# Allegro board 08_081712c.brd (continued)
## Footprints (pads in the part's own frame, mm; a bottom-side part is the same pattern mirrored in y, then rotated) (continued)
SWSML106W240H140
  rect 1.524x2.032 smd: 1(0,-4.516) 2(0,4.516)
SWSML335W142H220
  rect 0.991x1.6 smd: 1(-2.5,-1.2) 2(0,1.2) 3(2.5,-1.2)
SWSML837W244H153
  rect 1.092x1.499 smd: 1(-8.89,-4.451) 2(-6.35,-4.451) 3(-3.81,-4.451) 4(-1.27,-4.451) 5(1.27,-4.451) 6(3.81,-4.451) 7(6.35,-4.451) 8(8.89,-4.451) 9(8.89,4.451) 10(6.35,4.451) 11(3.81,4.451) 12(1.27,4.451) 13(-1.27,4.451) 14(-3.81,4.451) 15(-6.35,4.451) 16(-8.89,4.451)
SWSML858W263H160
  rect 1.118x2.438 smd: 1A(-8.89,-4.305) 1B(-8.89,4.305) 2A(-6.35,-4.305) 2B(-6.35,4.305) 3A(-3.81,-4.305) 3B(-3.81,4.305) 4A(-1.27,-4.305) 4B(-1.27,4.305) 5A(1.27,-4.305) 5B(1.27,4.305) 6A(3.81,-4.305) 6B(3.81,4.305) 7A(6.35,-4.305) 7B(6.35,4.305) 8A(8.89,-4.305) 8B(8.89,4.305)
SWSML1110W450H237
  rect 2.032x2.032 smd: 1(11.082,-4.42) 2(11.082,0) 3(11.082,4.42) 4(-8.776,4.414) 5(-8.776,-4.414)
TPC65D45
  round 1.651 hole 1.143: 1(0,0)
TPSMC30
  round 0.762 smd: 1(0,0)
TSSOP14
  rect 1.651x0.33 smd: 1(-2.87,1.956) 2(-2.87,1.306) 3(-2.87,0.655) 4(-2.87,0.005) 5(-2.87,-0.645) 6(-2.87,-1.295) 7(-2.87,-1.946) 8(2.87,-1.946) 9(2.87,-1.295) 10(2.87,-0.645) 11(2.87,0.005) 12(2.87,0.655) 13(2.87,1.306) 14(2.87,1.956)
unnamed
  round 4.445 hole 3.175 unplated: (0,0)
UPAK6
  rect 0.305x0.533 smd: 1(-0.5,-0.35)
  rect 0.305x0.483 smd: 2(0,-0.375) 3(0.5,-0.375) 4(0.5,0.375) 5(0,0.375) 6(-0.5,0.375)
UQFN12_2X1_7
  custom 0.102x0.102 smd: 1(-0.8,-0.655)
  rect 0.203x0.61 smd: 2(-0.4,-0.655) 3(0,-0.655) 4(0.4,-0.655) 5(0.8,-0.655) 7(0.8,0.655) 8(0.4,0.655) 9(0,0.655) 10(-0.4,0.655) 11(-0.8,0.655)
  rect 0.61x0.203 smd: 6(0.805,0) 12(-0.805,0)
VSSOP16
  rect 0.279x0.838 smd: 1(-1.75,-1.823) 2(-1.25,-1.823) 3(-0.75,-1.823) 4(-0.25,-1.823) 5(0.25,-1.823) 6(0.75,-1.823) 7(1.25,-1.823) 8(1.75,-1.823) 9(1.75,1.823) 10(1.25,1.823) 11(0.75,1.823) 12(0.25,1.823) 13(-0.25,1.823) 14(-0.75,1.823) 15(-1.25,1.823) 16(-1.75,1.823)
WLCSP4H26
  round 0.203 smd: A1(-0.2,-0.2) A2(-0.2,0.2) B1(0.2,-0.2) B2(0.2,0.2)
WSON8_5X6_PAD4X3_4
  oval 0.432x0.94 smd: 1(-1.905,-2.735) 2(-0.635,-2.735) 3(0.635,-2.735) 4(1.905,-2.735) 5(1.905,2.735) 6(0.635,2.735) 7(-0.635,2.735) 8(-1.905,2.735)
  rect 3.988x3.404 smd: PAD(0,0)
YSML79W63H32
  rect 0.762x0.66 smd: 1(-0.66,-0.508) 2(0.66,-0.508) 3(0.66,0.508) 4(-0.66,0.508)
YSML98W79H35
  rect 1.092x0.991 smd: 1(-0.921,-0.72) 2(0.921,-0.72) 3(0.921,0.72) 4(-0.921,0.72)
YSML126W59H26
  rect 0.991x1.803 smd: 1(-1.245,0) 2(1.245,0)
YSML126W98H31
  rect 1.397x1.194 smd: 1(-1.1,-0.95) 2(1.1,-0.95) 3(1.1,0.95) 4(-1.1,0.95)

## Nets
0V9: C18.1 C19.1 C20.1 C22.1 C28.1 C31.1 C70.1 C388.1 C389.1 L4.2(N2) TP14.1(N1) U1.4 U1.28 U1.36
0V9_B: C44.1 C45.1 C46.1 C48.1 C50.1 C52.1 C54.1 C57.1 C71.1 L3.2(N2) TP15.1(N1) U2.4 U2.28 U2.36
3V3: C17.1 C21.1 C25.1 C27.1 C29.1 C30.1 C43.1 C47.1 C49.1 C51.1 C53.1 C55.1 C56.1 C69.1 C76.1 C77.1 C78.1 C83.1 C84.1 C85.1 C86.1 C87.1 C88.1 C89.1 C90.1 C93.1 C94.1 C97.1 C98.1 C101.1 C102.1 C105.1 C106.1 C107.1 C108.1 C171.1 C172.1 C173.1 C177.1 C178.1 C184.1 C185.1 C187.1 C189.1 C190.1 C192.1 C193.1 C194.1 C195.1 C196.1 C197.1 C198.1 C315.2(N2) C317.1 C373.1 C374.1 C375.1 C378.1 C379.1 C380.1 C385.1 C387.1 C390.1 C393.1 C398.1 C429.1 C431.1 C432.1 L6.1 M1.1 M1.5 M2.1 M2.5 P1.20 P2.20 Q1.3(E) R68.1 R79.2(N2) R100.1 R111.2(N2) R127.1 R128.1 R129.1 R130.1 R131.2(N2) R132.2(N2) R138.2(N2) R140.2(N2) R267.1 R269.1 R271.1 R273.1 R284.1 R362.1 R363.1 R370.1 R371.1 R451.2(N2) R455.2(N2) R568.1 TP20.1(N1) U1.11 U1.20 U2.11 U2.20 U13.1 U13.2 U13.6 U16.11(REF_B) U17.11(REF_B) U18.4 U18.12 U18.31 U18.40 U19.4 U19.12 U19.31 U19.40 U20.11(REF_B) U21.11(REF_B) U30.11 U31.11 U32.11(REF_B) U33.3 U33.12 U33.22 U33.25 U33.39 U33.49 U33.58 U63.11(REF_B) U68.11(REF_B) U70.8(VCC) U71.5 U72.8(VCC) U73.5 U79.11(REF_B) U80.11(REF_B) U81.1 U81.12 Y1.1 Y1.4(VDD) Y2.1 Y2.4(VDD) Y3.1 Y3.4(VCC)
5V: A1.5 A2.5 C109.1 C110.1 C274.1 C275.1 C276.1 C277.1 C284.1 C285.1 C286.1 C287.1 C316.2(N2) C318.1 L7.1 R158.1 R161.1 R164.1 R167.1 R186.1 R189.1 R192.1 R195.1 R214.1 R217.1 R220.1 R223.1 R242.1 R245.1 R248.1 R251.1 R452.2(N2) R456.2(N2) TP21.1(N1) U41.14(VDD2) U42.14(VDD2) U43.14(VDD2) U44.14(VDD2)
5V_SOM_A: C419.2(N2) C420.1 L9.1 R592.2(N2) R594.2(N2) SOMA.E1 SOMA.E2 TP30.1(N1)
5V_SOM_B: C425.2(N2) C426.1 L10.1 R596.2(N2) R598.2(N2) SOMB.E1 SOMB.E2 TP31.1(N1)
10V: C111.1 C112.1 C125.1 C126.1 C139.1 C140.1 C153.1 C154.1 C304.2(N2) C306.1 L1.1 R442.2(N2) R446.2(N2) TP17.1(N1) U22.8 U23.8 U24.8 U25.8 U26.8 U27.8 U28.8 U29.8
12V: C302.2(N2) C307.1 C308.1 C319.1 C320.1 C421.1 C427.1 D10.C D11.C J4.95 J4.97 J4.99 J5.95 J5.97 J5.99 P3.95 P3.97 P3.99 P4.95 P4.97 P4.99 R460.2(N2) TP18.1(N1) TP19.1(N1) TP22.1(N1) U3.9(VIN) U4.9(VIN) U49.9(VIN) U50.9(VIN) U77.9(VIN) U78.9(VIN)
DGND: A1.2(V-) A2.2(V-) C1.2(N2) C2.2(N2) C3.2(N2) C4.2(N2) C5.2(N2) C6.2(N2) C7.2(N2) C8.2(N2) C9.2(N2) C10.2(N2) C11.2(N2) C12.2(N2) C13.2(N2) C14.1 C15.1 C16.1 C17.2(N2) C18.2(N2) C19.2(N2) C20.2(N2) C21.2(N2) C22.2(N2) C23.2(N2) C24.2(N2) C25.2(N2) C26.2(N2) C27.2(N2) C28.2(N2) C29.2(N2) C30.2(N2) C31.2(N2) C32.2(N2) C33.2(N2) C34.2(N2) C35.2(N2) C36.2(N2) C37.2(N2) C38.2(N2) C39.2(N2) C40.2(N2) C41.2(N2) C42.2(N2) C43.2(N2) C44.2(N2) C45.2(N2) C46.2(N2) C47.2(N2) C48.2(N2) C49.2(N2) C50.2(N2) C51.2(N2) C52.2(N2) C53.2(N2) C54.2(N2) C55.2(N2) C56.2(N2) C57.2(N2) C58.2(N2) C59.2(N2) C60.2(N2) C61.2(N2) C62.2(N2) C63.2(N2) C64.2(N2) C65.2(N2) C66.2(N2) C67.2(N2) C68.2(N2) C69.2(N2) C70.2(N2) C71.2(N2) C72.2(N2) C73.2(N2) C74.2(N2) C75.2(N2) C76.2(N2) C77.2(N2) C78.2(N2) C79.2(N2) C80.2(N2) C81.2(N2) C82.2(N2) C85.2(N2) C86.2(N2) C89.2(N2) C90.2(N2) C91.2(N2) C92.2(N2) C93.2(N2) C94.2(N2) C95.2(N2) C96.2(N2) C97.2(N2) C98.2(N2) C99.2(N2) C100.2(N2) C101.2(N2) C102.2(N2) C103.2(N2) C104.2(N2) C105.2(N2) C106.2(N2) C107.2(N2) C108.2(N2) C109.2(N2) C110.2(N2) C111.2(N2) C112.2(N2) C125.2(N2) C126.2(N2) C139.2(N2) C140.2(N2) C153.2(N2) C154.2(N2) C168.2(N2) C169.2(N2) C170.2(N2) C171.2(N2) C172.2(N2) C173.2(N2) C175.2(N2) C177.2(N2) C178.2(N2) C179.2(N2) C180.2(N2) C181.2(N2) C182.2(N2) C183.2(N2) C184.2(N2) C185.2(N2) C186.2(N2) C187.2(N2) C188.2(N2) C189.2(N2) C191.2(N2) C192.2(N2) C194.2(N2) C195.2(N2) C196.2(N2) C197.2(N2) C198.2(N2) C199.2(N2) C200.2(N2) C201.2(N2) C202.2(N2) C203.2(N2) C204.2(N2) C205.2(N2) C206.2(N2) C215.2(N2) C216.2(N2) C217.2(N2) C218.2(N2) C219.2(N2) C220.2(N2) C221.2(N2) C222.2(N2) C231.2(N2) C232.2(N2) C233.2(N2) C234.2(N2) C235.2(N2) C236.2(N2) C237.2(N2) C238.2(N2) C247.2(N2) C248.2(N2) C249.2(N2) C250.2(N2) C255.2(N2) C256.2(N2) C257.2(N2) C258.2(N2) C263.2(N2) C264.2(N2) C265.2(N2) C266.2(N2) C267.2(N2) C268.2(N2) C269.2(N2) C270.2(N2) C271.2(N2) C272.2(N2) C273.2(N2) C274.2(N2) C275.2(N2) C276.2(N2) C277.2(N2) C278.2(N2) C279.2(N2) C280.2(N2) C281.2(N2) C282.2(N2) C283.2(N2) C284.2(N2) C285.2(N2) C286.2(N2) C287.2(N2) C288.2(N2) C289.2(N2) C290.2(N2) C291.2(N2) C292.2(N2) C293.2(N2) C294.2(N2) C295.2(N2) C296.2(N2) C298.1 C300.2(N2) C301.2(N2) C302.1 C305.2(N2) C306.2(N2) C307.2(N2) C308.2(N2) C309.2(N2) C310.2(N2) C313.2(N2) C314.2(N2) C317.2(N2) C318.2(N2) C319.2(N2) C320.2(N2) C321.2(N2) C322.2(N2) C323.2(N2) C324.2(N2) C325.2(N2) C326.2(N2) C327.2(N2) C328.2(N2) C329.2(N2) C330.2(N2) C331.2(N2) C332.2(N2) C333.2(N2) C334.2(N2) C335.2(N2) C336.2(N2) C337.2(N2) C338.2(N2) C339.2(N2) C340.2(N2) C341.2(N2) C342.2(N2) C343.2(N2) C344.2(N2) C345.2(N2) C346.2(N2) C347.2(N2) C348.2(N2) C349.2(N2) C350.2(N2) C352.2(N2) C353.2(N2) C354.2(N2) C355.2(N2) C356.2(N2) C357.2(N2) C358.2(N2) C359.2(N2) C360.2(N2) C361.2(N2) C362.2(N2) C363.2(N2) C364.2(N2) C365.2(N2) C366.2(N2) C367.2(N2) C368.2(N2) C369.2(N2) C370.2(N2) C371.2(N2) C372.2(N2) C373.2(N2) C374.2(N2) C375.2(N2) C376.2(N2) C377.2(N2) C378.2(N2) C379.2(N2) C380.2(N2) C381.2(N2) C382.2(N2) C383.2(N2) C384.2(N2) C385.2(N2) C387.2(N2) C388.2(N2) C389.2(N2) C390.2(N2) C392.2(N2) C393.2(N2) C394.2(N2) C395.2(N2) C396.2(N2) C398.2(N2) C415.1 C416.2(N2) C418.2(N2) C420.2(N2) C421.2(N2) C422.2(N2) C424.2(N2) C426.2(N2) C427.2(N2) C428.2(N2) C429.2(N2) C430.2(N2) C431.2(N2) C432.2(N2) C433.2(N2) D1.2 D2.2 D3.2 D4.2 D5.3(N3) D6.3(N3) D7.3(N3) D8.3(N3) D9.A(P) D11.A(P) D13.2 DS21.C DS22.C J1.S J2.S J4.1 J4.2 J4.5 J4.6 J4.9 J4.10 J4.13 J4.14 J4.17 J4.18(N9) J4.21 J4.22 J4.25 J4.26 J4.29 J4.30 J4.33 J4.34 J4.37 J4.38 J4.41 J4.42 J4.45 J4.46 J4.49 J4.50 J4.53 J4.54 J4.57 J4.58 J4.61 J4.62 J4.65 J4.66 J4.69 J4.70 J4.73 J4.74 J4.77 J4.78 J4.81 J4.82 J4.86 J4.89 J4.90 J4.91 J4.92 J4.93 J4.94 J5.1 J5.2 J5.5 J5.6 J5.9 J5.10 J5.13 J5.14 J5.17 J5.18(N9) J5.21 J5.22 J5.25 J5.26 J5.29 J5.30 J5.33 J5.34 J5.37 J5.38 J5.41 J5.42 J5.45 J5.46 J5.49 J5.50 J5.53 J5.54 J5.57 J5.58 J5.61 J5.62 J5.65 J5.66 J5.69 J5.70 J5.73 J5.74 J5.77 J5.78 J5.81 J5.82 J5.86 J5.89 J5.90 J5.91 J5.92 J5.93 J5.94 M1.2 M1.6 M2.2 M2.6 P3.1 P3.2 P3.5 P3.6 P3.9 P3.10 P3.13 P3.14 P3.17 P3.18(N9) P3.21 P3.22 P3.25 P3.26 P3.29 P3.30 P3.33 P3.34 P3.37 P3.38 P3.41 P3.42 P3.45 P3.46 P3.49 P3.50 P3.53 P3.54 P3.57 P3.58 P3.61 P3.62 P3.65 P3.66 P3.69 P3.70 P3.73 P3.74 P3.77 P3.78 P3.81 P3.82 P3.86 P3.89 P3.90 P3.91 P3.92 P3.93 P3.94 P4.1 P4.2 P4.5 P4.6 P4.9 P4.10 P4.13 P4.14 P4.17 P4.18(N9) P4.21 P4.22 P4.25 P4.26 P4.29 P4.30 P4.33 P4.34 P4.37 P4.38 P4.41 P4.42 P4.45 P4.46 P4.49 P4.50 P4.53 P4.54 P4.57 P4.58 P4.61 P4.62 P4.65 P4.66 P4.69 P4.70 P4.73 P4.74 P4.77 P4.78 P4.81 P4.82 P4.86 P4.89 P4.90 P4.91 P4.92 P4.93 P4.94 P5.2 P5.4 P5.6 P5.8 P5.10 P5.12 P5.14 P5.16 P6.2 P6.4 P6.6 P6.8 P6.10 P6.12 P6.14 P6.16 P7.2 P7.3(N3) P9.A1 P9.A12 P9.B1 P9.B12 P9.GND1 P9.GND2 P9.SH1 P9.SH2 P9.SH3 P9.SH4 P9.SH5 P9.SH6 P11.1 P11.GND1 P11.GND2 P11.GND3 P11.GND4 P12.1 P12.GND1 P12.GND2 P12.GND3 P12.GND4 P13.1 P13.GND1 P13.GND2 P13.GND3 P13.GND4 P14.2A P14.2B P14.5A P14.5B P14.8A P14.8B P14.11A P14.11B P14.16A P14.16B P14.19A P14.19B P14.22A P14.22B P14.25A P14.25B P14.SH1 P14.SH2 P14.SH3 P14.SH4 P15.1 P15.GND1 P15.GND2 P15.GND3 P15.GND4 P16.2 P16.5 P16.8 P16.11 P16.16 P16.19 P16.22 P16.25 P18.1_3 P18.1_5 P18.1_6 P18.2_3 P18.2_5 P18.2_6 P19.1_3 P19.1_5 P19.1_6 P19.2_3 P19.2_5 P19.2_6 P20.2 P20.4 P20.6 P20.8 P20.10 P20.12 P20.14 P20.16 P20.18 P20.20 P21.2 P21.4 P21.6 P21.8 P21.10 P21.12 P21.14 P21.16 P21.18 P21.20 P22.1 P23.1 P24.1 P25.1 P26.1 P27.1 P30.8 P30.12 P31.8 P31.12 P32.5 P32.7 P32.9(N9) P32.11 P33.5 P33.7 P33.9(N9) P33.11 P34.3 P34.5 P35.3 P35.5 P35.15 P35.17 P35.19 P37.1 P37.2 P37.11 P37.12 P38.4(N4) P39.2 P39.4 P39.6 P39.8 P39.10 P39.12 P39.14 P39.16 P39.18 P39.20 P40.2 P40.4 P40.6 P40.8 P40.10 P40.12 P40.14 P40.16 P40.18 P40.20 P42.4(N4) PB1.1 PB1.2(NO) PB2.1 PB2.2(NO) PB3.1 PB3.2(NO) PB4.1 PB4.2(NO) R22.2(N2) R23.2(N2) R25.2(N2) R26.2(N2) R27.2(N2) R28.2(N2) R29.2(N2) R30.2(N2) R34.2(N2) R36.2(N2) R51.2(N2) R53.1 R55.1 R57.1 R59.1 R61.1 R67.1 R72.1 R75.1 R77.1 R80.1 R85.1 R87.1 R89.1 R91.1 R93.1 R99.1 R104.1 R107.1 R109.1 R112.1 R117.2(N2) R119.2(N2) R121.2(N2) R122.2(N2) R124.2(N2) R125.2(N2) R133.2(N2) R134.2(N2) R137.2(N2) R139.2(N2) R149.2(N2) R150.2(N2) R153.2(N2) R154.2(N2) R155.2(N2) R156.2(N2) R177.2(N2) R178.2(N2) R179.2(N2) R180.2(N2) R181.2(N2) R182.2(N2) R183.2(N2) R184.2(N2) R205.2(N2) R206.2(N2) R207.2(N2) R208.2(N2) R209.2(N2) R210.2(N2) R211.2(N2) R212.2(N2) R233.2(N2) R234.2(N2) R235.2(N2) R236.2(N2) R237.2(N2) R238.2(N2) R239.2(N2) R240.2(N2) R261.2(N2) R262.2(N2) R263.2(N2) R264.2(N2) R266.2(N2) R278.2(N2) R282.2(N2) R283.2(N2) R293.2(N2) R294.2(N2) R295.2(N2) R296.2(N2) R297.2(N2) R298.2(N2) R299.2(N2) R300.2(N2) R309.2(N2) R310.2(N2) R311.2(N2) R312.2(N2) R313.2(N2) R314.2(N2) R315.2(N2) R316.2(N2) R325.2(N2) R326.2(N2) R327.2(N2) R328.2(N2) R329.2(N2) R330.2(N2) R331.2(N2) R332.2(N2) R337.2(N2) R338.2(N2) R339.2(N2) R340.2(N2) R345.2(N2) R346.2(N2) R347.2(N2) R348.2(N2) R349.2(N2) R350.2(N2) R351.2(N2) R352.2(N2) R353.2(N2) R354.2(N2) R355.2(N2) R356.2(N2) R357.2(N2) R364.2(N2) R365.2(N2) R384.1 R385.1 R386.1 R387.1 R408.2(N2) R409.2(N2) R410.2(N2) R411.2(N2) R420.2(N2) R421.2(N2) R422.2(N2) R423.2(N2) R424.2(N2) R425.2(N2) R426.2(N2) R427.2(N2) R428.2(N2) R429.2(N2) R430.2(N2) R431.2(N2) R438.2(N2) R439.2(N2) R440.2(N2) R443.2(N2) R444.2(N2) R447.2(N2) R448.2(N2) R449.2(N2) R450.2(N2) R453.2(N2) R454.2(N2) R457.2(N2) R458.2(N2) R459.1 R463.2(N2) R465.2(N2) R473.2(N2) R479.2(N2) R480.2(N2) R482.2(N2) R483.2(N2) R491.2(N2) R496.2(N2) R504.2(N2) R505.2(N2) R506.2(N2) R507.2(N2) R508.2(N2) R522.2(N2) R523.2(N2) R524.2(N2) R525.2(N2) R533.2(N2) R534.2(N2) R537.2(N2) R538.2(N2) R541.2(N2) R542.2(N2) R545.2(N2) R550.2(N2) R553.2(N2) R556.2(N2) R557.2(N2) R564.2(N2) R567.2(N2) R569.2(N2) R572.2(N2) R590.2(N2) R591.2(N2) R593.2(N2) R595.2(N2) R597.2(N2) S1.3(NO) S2.3(NO) S14.2(NO) SOMA.27 SOMA.28 SOMA.49 SOMA.50 SOMA.71 SOMA.72 SOMA.73 SOMA.85 SOMA.90 SOMA.97 SOMA.109 SOMA.110 SOMA.121 SOMA.124 SOMA.133 SOMA.134 SOMA.145 SOMA.148 SOMA.154 SOMA.157 SOMA.160 SOMA.166 SOMA.169 SOMA.174 SOMA.180 SOMA.181 SOMA.186 SOMA.191 SOMA.193 SOMA.196 SOMA.203 SOMA.206 SOMA.213 SOMA.216 SOMA.223 SOMA.229 SOMA.235 SOMA.238 SOMA.251 SOMA.260 SOMA.262 SOMA.265 SOMA.268 SOMA.272 SOMA.278 SOMA.279 SOMA.280 SOMA.281 SOMA.E3 SOMA.E4 SOMA.SH1 SOMA.SH2(N2) SOMB.27 SOMB.28 SOMB.49 SOMB.50 SOMB.71 SOMB.72 SOMB.73 SOMB.85 SOMB.90 SOMB.97 SOMB.109 SOMB.110 SOMB.121 SOMB.124 SOMB.133 SOMB.134 SOMB.145 SOMB.148 SOMB.154 SOMB.157 SOMB.160 SOMB.166 SOMB.169 SOMB.174 SOMB.180 SOMB.181 SOMB.186 SOMB.191 SOMB.193 SOMB.196 SOMB.203 SOMB.206 SOMB.213 SOMB.216 SOMB.223 SOMB.229 SOMB.235 SOMB.238 SOMB.251 SOMB.260 SOMB.262 SOMB.265 SOMB.268 SOMB.272 SOMB.278 SOMB.279 SOMB.280 SOMB.281 SOMB.E3 SOMB.E4 SOMB.SH1 SOMB.SH2(N2) TP25.1(N1) TP26.1(N1) TP27.1(N1) TP28.1(N1) TP29.1(N1) U1.5 U1.PAD U2.5 U2.PAD U3.PAD U4.PAD U5.2 U6.2 U7.7 U8.19 U8.PAD U9.7 U9.11 U9.12 U10.2 U11.3 U12.3 U13.3 U13.PAD U14.8 U15.8 U16.6 U17.6 U18.1 U18.5 U18.11 U18.21 U18.22 U18.28 U18.29 U18.PAD U19.1 U19.5 U19.11 U19.21 U19.22 U19.28 U19.29 U19.PAD U20.6 U21.6 U22.4(-VS) U23.4(-VS) U24.4(-VS) U25.4(-VS) U26.4(-VS) U27.4(-VS) U28.4(-VS) U29.4(-VS) U30.6 U31.6 U32.6 U33.13 U33.14 U33.21 U33.26 U33.30 U33.40 U33.48 U33.61 U33.80 U34.8 U35.8 U36.8 U37.8 U38.8 U39.8 U40.8 U41.2 U41.8 U41.9 U41.13 U41.16 U42.2 U42.8 U42.9 U42.13 U42.16 U43.2 U43.8 U43.9 U43.13 U43.16 U44.2 U44.8 U44.9 U44.13 U44.16 U45.8 U46.8 U47.8 U48.8 U49.PAD U50.PAD U51.19 U51.PAD U52.8 U52.12 U52.13 U52.14 U53.4 U53.PAD U54.B3 U54.B5 U54.C5 U54.D3 U54.D9 U54.D10 U54.E2 U54.E3 U54.H10 U54.K4 U54.K8 U55.PAD U56.1 U57.B2 U58.8 U58.9 U58.PAD U59.3 U60.2 U60.3 U60.8 U60.9 U60.PAD U61.8 U61.9 U61.10 U61.11 U61.12 U61.13 U61.14 U62.8 U62.9 U62.10 U62.11 U62.12 U62.13 U62.14 U63.6 U64.3 U65.B3 U65.C1 U65.E5(VSSQ_2) U66.1 U66.9 U67.5 U67.6 U67.7 U67.8 U67.12 U67.13 U67.14 U68.6 U69.5 U69.6 U69.7 U69.8 U69.12 U69.13 U69.14 U70.5 U71.3 U72.5 U73.3 U74.7 U75.7 U76.2 U77.PAD U78.PAD U79.6 U80.4 U80.5 U80.6 U80.7 U80.8 U81.4 U81.5 U81.6 U81.7(YB4) U81.8 Y1.2 Y2.2 Y3.2 Y6.2 Y6.4
GND_FIELD: P1.13 P1.14 P1.SH1 P1.SH2 P2.13 P2.14 P2.SH1 P2.SH2
VBUS_DETECT: C345.1 R481.2(N2) R482.1 U54.J11
VDDIO: C5.1 C6.1 C7.1 C8.1 C9.1 C10.1 C11.1 C12.1 C13.1 C14.2(N2) C15.2(N2) C16.2(N2) C23.1 C24.1 C26.1 C32.1 C33.1 C34.1 C35.1 C36.1 C38.1 C42.1 C58.1 C59.1 C60.1 C61.1 C62.1 C64.1 C68.1 C72.1 C73.1 C74.1 C75.1 C91.1 C92.1 C168.1 C169.1 C170.1 C263.1 C264.1 C265.1 C266.1 C267.1 C268.1 C269.1 C270.1 C271.1 C272.1 C273.1 C280.1 C281.1 C282.1 C283.1 C290.1 C291.1 C292.1 C293.1 C295.1 C303.2(N2) C305.1 C369.1 C370.1 C371.1 C372.1 C376.1 C377.1 C381.1 C382.1 C394.1 C396.1 C428.1 C430.1 C433.1 DS23.A(P) L5.1 P1.17 P2.17 R2.1 R3.1 R4.1 R5.1 R6.1 R7.1 R13.1 R14.1 R15.1 R16.1 R21.1 R24.1 R31.1 R32.1 R33.1 R35.1 R50.1 R52.2(N2) R54.2(N2) R58.2(N2) R60.2(N2) R62.2(N2) R66.2(N2) R71.2(N2) R74.2(N2) R76.2(N2) R78.1 R81.1 R84.2(N2) R86.2(N2) R90.2(N2) R92.2(N2) R94.2(N2) R98.2(N2) R103.2(N2) R106.2(N2) R108.2(N2) R110.1 R113.1 R120.1 R432.2(N2) R433.2(N2) R434.2(N2) R435.2(N2) R436.2(N2) R437.2(N2) R441.2(N2) R445.2(N2) R462.1 R509.2(N2) R510.2(N2) R511.2(N2) R512.2(N2) R513.2(N2) R514.1 R517.1 R528.1 R529.1 R530.1 R531.1 R535.1 R536.1 R539.1 R540.1 R543.1 R544.1 R546.1 R547.1 R548.1 R549.1 R551.1 R554.1 R555.1 R558.1 R559.1 R560.1 R561.1 R562.1 R563.1 R585.1 R588.1 R589.1 S11.1 S15.2(B) TP16.1(N1) U1.25 U1.31 U1.40 U2.25 U2.31 U2.40 U5.5(VCC) U6.5(VCC) U7.14(VCC) U8.21(VCC) U9.14(VCC) U10.4 U11.6 U12.6 U14.16(VCC) U15.16(VCC) U16.1 U16.12 U17.1 U17.12 U20.1 U20.12 U21.1 U21.12 U30.1 U30.12 U31.1 U31.12 U32.1 U32.12 U34.16(VCC) U35.16(VCC) U36.16(VCC) U37.16(VCC) U38.16(VCC) U39.16(VCC) U40.16(VCC) U41.1 U42.1 U43.1 U44.1 U45.16(VCC) U46.16(VCC) U47.16(VCC) U48.16(VCC) U51.21(VCC) U52.16(VCC) U61.16(VCC) U62.16(VCC) U63.1 U63.12 U64.5 U65.B4 U65.D1 U65.E4 U66.4(VM) U66.5 U67.16(VCC) U68.1 U68.12 U69.16(VCC) U74.14(VCC) U75.14(VCC) U76.4 U79.1 U79.12 U80.1 U80.12 U81.11
24.576MHZ: P36.1 R126.2(N2) S16.3A S16.4A
24.576MHZ_SOMA: R502.2(N2) U81.2
24.576MHZ_SOMB: R503.2(N2) U81.3
_N11: P1.18 R83.1
_N12: R57.2(N2) U1.10
_N13: R70.2(N2) U1.35
_N14: R65.2(N2) U1.34
_N15: P1.19 R82.1
_N16: R73.2(N2) U1.29
_N17: R69.2(N2) U1.30
_N18: R64.2(N2) U1.32
_N19: R63.2(N2) U1.33
_N20: C37.1 C39.1 C40.1 C41.1 P1.1 P1.6 P1.7 P1.12
_N41: P2.18 R115.1
_N42: R89.2(N2) U2.10
_N43: R102.2(N2) U2.35
_N44: R97.2(N2) U2.34
_N45: P2.19 R114.1
_N46: R105.2(N2) U2.29
_N47: R101.2(N2) U2.30
_N48: R96.2(N2) U2.32
_N49: R95.2(N2) U2.33
_N50: C63.1 C65.1 C66.1 C67.1 P2.1 P2.6 P2.7 P2.12
_N114: L3.1 R116.1 U13.5(VOUT2)
_N115: L4.1 R118.1 U13.7
_N116: R116.2(N2) R117.1 U13.4
_N117: R118.2(N2) R119.1 U13.8
_N448: R20.2(N2) U7.12
_N450: PB3.3 R11.1
_N451: PB4.3 R12.1
_N452: R20.1 U6.4
_N453: R19.1 U6.6
_N454: C3.1 R11.2(N2) R15.2(N2) U6.1
_N455: C4.1 R12.2(N2) R16.2(N2) U6.3
_N552: C137.P R203.2(N2)
_N554: C138.P R204.2(N2)
_N555: C130.N(N2) R194.1
_N556: C129.N(N2) R188.1
_N557: C121.P R173.2(N2)
_N558: C116.N(N2) R166.1
_N559: C122.P R174.2(N2)
_N560: C123.P R175.2(N2)
_N561: C124.P R176.2(N2)
_N562: C115.N(N2) R160.1
_N563: C135.P R201.2(N2)
_N566: C136.P R202.2(N2)
_N568: R189.2(N2) R190.2(N2) U24.5
_N569: C132.1 R188.2(N2) R198.1 U24.6
_N570: C133.2(N2) R199.2(N2) R203.1 U25.1
_N571: R192.2(N2) R193.2(N2) U25.3
_N572: C133.1 R191.2(N2) R199.1 U25.2
_N574: R195.2(N2) R196.2(N2) U25.5
_N575: C134.1 R194.2(N2) R200.1 U25.6
_N577: C117.1 R157.2(N2) R169.1 U22.2
_N578: R158.2(N2) R159.2(N2) U22.3
_N580: R161.2(N2) R162.2(N2) U22.5
_N581: C118.1 R160.2(N2) R170.1 U22.6
_N582: C119.2(N2) R171.2(N2) R175.1 U23.1
_N583: R164.2(N2) R165.2(N2) U23.3
_N584: C119.1 R163.2(N2) R171.1 U23.2
_N586: R167.2(N2) R168.2(N2) U23.5
_N587: C120.1 R166.2(N2) R172.1 U23.6
_N588: C131.2(N2) R197.2(N2) R201.1 U24.1
_N589: R186.2(N2) R187.2(N2) U24.3
_N590: C131.1 R185.2(N2) R197.1 U24.2
_N672: C165.P R259.2(N2)
_N674: C166.P R260.2(N2)
_N675: C158.N(N2) R250.1
_N676: C157.N(N2) R244.1
_N677: C149.P R229.2(N2)
_N678: C144.N(N2) R222.1
_N679: C150.P R230.2(N2)
_N680: C151.P R231.2(N2)
_N681: C152.P R232.2(N2)
_N682: C143.N(N2) R216.1
_N683: C163.P R257.2(N2)
_N686: C164.P R258.2(N2)
_N688: R245.2(N2) R246.2(N2) U28.5
_N689: C160.1 R244.2(N2) R254.1 U28.6
_N690: C161.2(N2) R255.2(N2) R259.1 U29.1
_N691: R248.2(N2) R249.2(N2) U29.3
_N692: C161.1 R247.2(N2) R255.1 U29.2
_N694: R251.2(N2) R252.2(N2) U29.5
_N695: C162.1 R250.2(N2) R256.1 U29.6
_N696: C145.2(N2) R225.2(N2) R229.1 U26.1
_N697: C145.1 R213.2(N2) R225.1 U26.2
_N698: R214.2(N2) R215.2(N2) U26.3
_N700: R217.2(N2) R218.2(N2) U26.5
_N701: C146.1 R216.2(N2) R226.1 U26.6
_N702: C147.2(N2) R227.2(N2) R231.1 U27.1
_N703: R220.2(N2) R221.2(N2) U27.3
_N704: C147.1 R219.2(N2) R227.1 U27.2
_N706: R223.2(N2) R224.2(N2) U27.5
_N707: C148.1 R222.2(N2) R228.1 U27.6
_N708: C159.2(N2) R253.2(N2) R257.1 U28.1
_N709: R242.2(N2) R243.2(N2) U28.3
_N710: C159.1 R241.2(N2) R253.1 U28.2
_N761: R438.1 U49.4
_N762: C294.1 U49.3
_N763: C297.2(N2) U49.1
_N764: C301.1 U49.7
_N765: C304.1 R444.1 R446.1 U49.6
_N766: R442.1 U49.8
_N767: C297.1 L1.2(N2) U49.2
_N778: Q1.1 R284.2(N2) U33.24
_N780: C174.2(N2) C175.1 C179.1 C180.1 Q1.2 Q1.4 R280.2(N2) U33.16 U33.20 U33.23 U33.29 U33.41
_N784: C181.1 C182.1 U33.62
_N787: C183.1 C186.1 U33.63
_N789: C188.1 U33.1
_N790: C191.1 U33.60
_N791: C193.2(N2) U33.2
_N792: C190.2(N2) U33.59
_N798: R283.1 U33.46
_N799: R282.1 U33.45
_N800: R278.1 U33.42
_N829: R19.2(N2) U7.9
_N831: C278.1 R358.2(N2) R359.1
_N832: D5.2 P18.1_7 R359.2(N2) U41.12
_N833: D5.1 P18.1_2 R358.1 U41.11
_N836: R356.1 U41.10
_N863: C279.1 R360.2(N2) R361.1
_N864: D6.2 P18.2_7 R361.2(N2) U42.12
_N865: D6.1 P18.2_2 R360.1 U42.11
_N866: P18.2_9(N9) R363.2(N2)
_N867: R357.1 U42.10
_N873: P18.1_9 R362.2(N2)
_N894: C288.1 R366.2(N2) R367.1
_N895: D7.2 P19.1_7 R367.2(N2) U43.12
_N896: D7.1 P19.1_2 R366.1 U43.11
_N897: R364.1 U43.10
_N898: C289.1 R368.2(N2) R369.1
_N899: D8.2 P19.2_7 R369.2(N2) U44.12
_N900: D8.1 P19.2_2 R368.1 U44.11
_N901: P19.2_9(N9) R371.2(N2)
_N902: R365.1 U44.10
_N903: P19.1_9 R370.2(N2)
_N916: R268.1 U30.10
_N917: R270.1 U30.9
_N918: R272.1 U30.8
_N919: R275.1 U30.7(YB4)
_N920: R268.2(N2) U33.27
_N921: R270.2(N2) U33.28
_N922: R272.2(N2) U33.38
_N923: R275.2(N2) U33.37
_N935: R274.1 U31.10
_N937: R277.1 U31.8
_N938: R279.1 U31.7(YB4)
_N939: R271.2(N2) U32.10 U33.43
_N940: R273.2(N2) U32.9 U33.44
_N942: R276.1 U31.9
_N943: R274.2(N2) U33.36
_N944: R276.2(N2) U33.35
_N945: R279.2(N2) U33.33
_N946: R277.2(N2) U33.34
_N948: R269.2(N2) U32.7 U33.47
_N956: C174.1 C176.1 U33.15
_N957: C176.2(N2) R280.1
_N962: C203.1 C211.P C399.1 R289.2(N2)
_N965: C87.2(N2) R151.2(N2) U18.3
_N982: C83.2(N2) R151.1
_N983: C79.1 C81.1 R149.1 U18.10
_N985: A1.3 C95.1 C99.1 C103.1 U18.2(VREF)
_N988: R145.1 U18.13
_N989: R141.1 U18.14
_N990: R146.1 U18.15
_N991: R142.1 U18.16
_N992: R142.2(N2) U20.7
_N993: R146.2(N2) U20.8
_N994: R141.2(N2) U20.9
_N995: R145.2(N2) U20.10
_N996: R127.2(N2) U16.8 U18.18
_N997: R129.2(N2) U16.7 U18.17
_N998: R131.1 U16.9 U18.6
_N1002: R133.1 U18.9
_N1003: R137.1 U18.19
_N1004: R139.1 U18.20
_N1005: R135.2(N2) U18.7
_N1045: C88.2(N2) R152.2(N2) U19.3
_N1046: C84.2(N2) R152.1
_N1047: C80.1 C82.1 R150.1 U19.10
_N1048: A2.3 C96.1 C100.1 C104.1 U19.2(VREF)
_N1049: R147.1 U19.13
_N1050: R143.1 U19.14
_N1051: R148.1 U19.15
_N1052: R144.1 U19.16
_N1053: R144.2(N2) U21.7
_N1054: R148.2(N2) U21.8
_N1055: R143.2(N2) U21.9
_N1056: R147.2(N2) U21.10
_N1057: R128.2(N2) U17.8 U19.18
_N1058: R130.2(N2) U17.7 U19.17
_N1059: R132.1 U17.9 U19.6
_N1060: R134.1 U19.9
_N1061: R138.1 U19.19
_N1062: R140.1 U19.20
_N1063: R136.2(N2) U19.7
_N1086: P36.2(N2) R281.2(N2) U33.17
_N1090: R265.2(N2) U32.4
_N1095: R123.2(N2) U16.2
_N1105: C204.1 C212.P C399.2(N2) R290.2(N2)
_N1117: R376.2(N2) R384.2(N2) R392.1
_N1122: R377.2(N2) R386.2(N2) R393.1
_N1134: R372.2(N2) R388.1
_N1138: R373.2(N2) R389.1
_N1142: R374.2(N2) R390.1
_N1146: R375.2(N2) R391.1
_N1196: R382.2(N2) R385.2(N2) R398.1
_N1197: R383.2(N2) R387.2(N2) R399.1
_N1198: R378.2(N2) R394.1
_N1199: R379.2(N2) R395.1
_N1200: R380.2(N2) R396.1
_N1201: R381.2(N2) R397.1
_N1233: R1.2(N2) SOMA.111
_N1244: C205.1 C213.P C400.1 R291.2(N2)
_N1245: C206.1 C214.P C400.2(N2) R292.2(N2)
_N1250: C199.1 C207.P C401.1 R285.2(N2)
_N1251: C200.1 C208.P C401.2(N2) R286.2(N2)
_N1256: C201.1 C209.P C402.1 R287.2(N2)
_N1257: C202.1 C210.P C402.2(N2) R288.2(N2)
_N1276: C219.1 C227.P C403.1 R305.2(N2)
_N1277: C220.1 C228.P C403.2(N2) R306.2(N2)
_N1278: C221.1 C229.P C404.1 R307.2(N2)
_N1279: C222.1 C230.P C404.2(N2) R308.2(N2)
_N1280: C215.1 C223.P C405.1 R301.2(N2)
_N1281: C216.1 C224.P C405.2(N2) R302.2(N2)
_N1282: C217.1 C225.P C406.1 R303.2(N2)
_N1283: C218.1 C226.P C406.2(N2) R304.2(N2)
_N1300: C235.1 C243.P C407.1 R321.2(N2)
_N1301: C236.1 C244.P C407.2(N2) R322.2(N2)
_N1302: C237.1 C245.P C408.1 R323.2(N2)
_N1303: C238.1 C246.P C408.2(N2) R324.2(N2)
_N1304: C231.1 C239.P C409.1 R317.2(N2)
_N1305: C232.1 C240.P C409.2(N2) R318.2(N2)
_N1306: C233.1 C241.P C410.1 R319.2(N2)
_N1307: C234.1 C242.P C410.2(N2) R320.2(N2)
_N1324: C247.1 C251.P C411.1 R333.2(N2)
_N1325: C248.1 C252.P C411.2(N2) R334.2(N2)
_N1326: C249.1 C253.P C412.1 R335.2(N2)
_N1327: C250.1 C254.P C412.2(N2) R336.2(N2)
_N1336: C255.1 C259.P C413.1 R341.2(N2)
_N1337: C256.1 C260.P C413.2(N2) R342.2(N2)
_N1338: C257.1 C261.P C414.1 R343.2(N2)
_N1339: C258.1 C262.P C414.2(N2) R344.2(N2)
_N1376: C117.2(N2) R169.2(N2) R173.1 U22.1
_N1392: C113.N(N2) S3.1
_N1393: R157.1 S3.2
_N1395: C114.N(N2) S4.1
_N1396: R163.1 S4.2
_N1398: C127.N(N2) S5.1
_N1399: R185.1 S5.2
_N1401: C128.N(N2) S6.1
_N1402: R191.1 S6.2
_N1404: C141.N(N2) S7.1
_N1405: R213.1 S7.2
_N1407: C142.N(N2) S8.1
_N1408: R219.1 S8.2
_N1410: R241.1 S9.2
_N1411: C155.N(N2) S9.1
_N1413: C156.N(N2) S10.1
_N1414: R247.1 S10.2
_N1418: R349.1 U34.15
_N1461: R350.1 U35.15
_N1496: R351.1 U36.15
_N1497: R352.1 U37.15
_N1508: R353.1 U38.15
_N1509: R354.1 U39.15
_N1534: R355.1 U40.15
_N1575: R56.1 Y1.3
_N1581: R408.1 U45.15
_N1583: U45.2 U47.2
_N1584: U45.5 U47.5
_N1585: U45.11 U47.11
_N1586: U45.14 U47.14
_N1598: R410.1 U47.15
_N1602: R403.2(N2) U45.12
_N1603: R402.2(N2) U45.9
_N1604: R401.2(N2) U45.7
_N1605: R400.2(N2) U45.4
_N1606: R412.1 U47.4
_N1607: R413.1 U47.7
_N1608: R414.1 U47.9
_N1609: R415.1 U47.12
_N1616: DS16.C R429.1
_N1617: DS17.C R430.1
_N1618: DS18.C R431.1
_N1619: DS14.C R427.1
_N1620: DS15.C R428.1
_N1621: DS13.C R426.1
_N1696: R136.1 S16.2B S16.4B S16.6B S16.8B(N9)
_N1726: R409.1 U46.15
_N1727: U46.2 U48.2
_N1728: U46.5 U48.5
_N1729: U46.11 U48.11
_N1730: U46.14 U48.14
_N1731: R411.1 U48.15
_N1732: R407.2(N2) U46.12
_N1733: R406.2(N2) U46.9
_N1734: R405.2(N2) U46.7
_N1735: R404.2(N2) U46.4
_N1736: R416.1 U48.4
_N1737: R417.1 U48.7
_N1738: R418.1 U48.9
_N1739: R419.1 U48.12
_N1774: DS1.C R23.1
_N1775: DS2.C R26.1
_N1776: DS3.C R27.1
_N1800: DS4.C R28.1
_N1801: DS5.C R29.1
_N1802: DS6.C R30.1
_N1808: R8.2(N2) SOMB.111
_N1810: R56.2(N2) U1.9
_N1813: R88.1 Y2.3
_N1815: R88.2(N2) U2.9
_N1851: R126.1 R502.1 R503.1 Y3.3
_N1863: R121.1 U14.15
_N1867: R122.1 U15.15
_N1869: R120.2(N2) S2.1
_N1910: R39.2(N2) U65.A3
_N1911: R37.2(N2) U65.C2
_N1912: R41.1 U65.C3
_N1913: R43.1 U65.D4
_N1914: R46.1 U65.D2
_N1915: R42.1 U65.D3
_N1916: R38.2(N2) U65.B2
_N1917: R49.1 U65.E1
_N1918: R44.1 U65.D5
_N1919: R48.1 U65.E3
_N1920: R47.1 U65.C4
_N1921: R45.1 U65.E2
_N1922: R40.2(N2) U65.B1
_N1956: P30.15 R516.1
_N1957: DS21.A(P) R516.2(N2)
_N1976: P31.15 R519.1
_N1977: DS22.A(P) R519.2(N2)
_N1980: P31.6 R517.2(N2) R518.1
_N1981: P30.6 R514.2(N2) R515.1
_N2048: R524.1 U61.15
_N2049: U61.2 U62.2
_N2050: U61.5 U62.5
_N2053: R525.1 U62.15
_N2056: R521.2(N2) U61.7
_N2057: R520.2(N2) U61.4
_N2058: R526.1 U62.4
_N2059: R527.1 U62.7
_N2133: DS23.C R552.1
_N2134: R549.2(N2) U66.3
_N2135: R550.1 U66.6
_N2136: R548.2(N2) U64.4(Y) U66.2
_N2137: C395.1 U66.7
_N2144: DS24.A(P) U61.3
_N2145: DS19.A(P) U61.6
_N2146: DS25.A(P) U62.3
_N2147: DS26.A(P) U62.6
_N2150: DS19.C R449.1
_N2154: DS24.C R450.1
_N2157: DS25.C R457.1
_N2160: DS26.C R458.1
_N2166: R462.2(N2) S1.1
_N2171: R522.1 U52.15
_N2179: P8.1 R531.2(N2)
_N2180: P8.10 R532.2(N2)
_N2192: R533.1 U67.15
_N2202: R534.1 U69.15
_N2225: C167.1 R267.2(N2) R565.1 U70.1
_N2226: C384.1 R564.1 R565.2(N2) U70.2
_N2229: C167.2(N2) J1.T2
_N2232: C386.1 U71.4(Y)
_N2233: C386.2(N2) R566.1
_N2248: C391.1 R568.2(N2) R570.1 U72.1
_N2249: C392.1 R569.1 R570.2(N2) U72.2
_N2251: C391.2(N2) J2.T2
_N2252: C397.1 U73.4(Y)
_N2253: C397.2(N2) R571.1
_N2262: R573.2(N2) U63.2
_N2263: R574.2(N2) U63.3
_N2264: R576.2(N2) U63.5
_N2265: R575.2(N2) U63.4
_N2272: R577.2(N2) U33.19
_N2408: R578.2(N2) U68.2
_N2409: R580.2(N2) U68.4
_N2414: R581.2(N2) U68.5
_N2415: R579.2(N2) U68.3
_N2416: P17.3(N3) R461.1
_N2417: P17.1 R460.1
_N2430: R582.2(N2) U17.2
_N2436: S16.7A S16.8A U17.10
_N2437: R135.1 S16.1B S16.3B S16.5B S16.7B
_N2439: S16.1A S16.2A U16.10
_N2453: P35.10 R583.1 R584.1
_N2454: P35.1 R585.2(N2)
_N2460: R586.1 SOMA.274
_N2463: R587.1 SOMB.274
_N2470: U67.2 U74.2 U74.5
_N2471: U67.11 U74.9 U74.12
_N2476: R573.1 U74.3
_N2477: R574.1 U74.6
_N2478: R575.1 U74.8
_N2479: R576.1 U74.11
_N2500: U69.2 U75.2 U75.5
_N2501: U69.11 U75.9 U75.12
_N2502: R578.1 U75.3
_N2503: R579.1 U75.6
_N2504: R580.1 U75.8
_N2505: R581.1 U75.11
_N2535: C418.1 U77.7
_N2536: C417.1 L9.2(N2) U77.2
_N2537: R591.1 U77.4
_N2538: R592.1 U77.8
_N2539: C416.1 U77.3
_N2540: C419.1 R593.1 R594.1 U77.6
_N2541: C417.2(N2) U77.1
_N2565: C424.1 U78.7
_N2566: C423.1 L10.2(N2) U78.2
_N2567: R595.1 U78.4
_N2568: R596.1 U78.8
_N2569: C422.1 U78.3
_N2570: C425.1 R597.1 R598.1 U78.6
_N2571: C423.2(N2) U78.1
_N2633: R599.1 U54.N4
_N2642: PB1.3 R9.1
_N2684: PB1.5 R600.1
_N2688: PB2.5 R601.1
_N2692: PB3.5 R602.1
_N2696: PB4.5 R603.1
_N2698: C383.1 R546.2(N2) S14.3 U64.1
`: J1.T1 J2.T1 R566.2(N2) R567.1 R571.2(N2) R572.1
A0N_FB: C118.2(N2) R170.2(N2) R174.1 S3.3(NO) U22.7
A1N_FB: C120.2(N2) R172.2(N2) R176.1 S4.3(NO) U23.7
A2B1_IO1: DS7.A(P) J4.52 U8.14
A2B1_IO2: DS8.A(P) J4.48 U8.15
A2B1_IO7: DS9.A(P) J4.44 U8.16
A2B1_IRQ: J4.60 SOMA.227
A2B1_RESET: J4.56 SOMA.225
A2B2_IO1: DS10.A(P) J5.52 U8.17
A2B2_IO2: DS11.A(P) J5.48 U8.18
A2B2_IO7: DS12.A(P) J5.44
A2B2_IRQ: J5.60 SOMA.233
A2B2_RESET: J5.56 SOMA.231
A2B3_IO1: DS13.A(P) P3.52 U51.14
A2B3_IO2: DS14.A(P) P3.48 U51.15
A2B3_IO7: DS15.A(P) P3.44 U51.16
A2B3_IRQ: P3.60 SOMB.227
A2B3_RESET: P3.56 SOMB.225
A2B4_IO1: DS16.A(P) P4.52 U51.17
A2B4_IO2: DS17.A(P) P4.48 U51.18
A2B4_IO7: DS18.A(P) P4.44
A2B4_IRQ: P4.60 SOMB.233
A2B4_RESET: P4.56 SOMB.231
A2N_FB: C132.2(N2) R198.2(N2) R202.1 S5.3(NO) U24.7
A3N_FB: C134.2(N2) R200.2(N2) R204.1 S6.3(NO) U25.7
A4N_FB: C146.2(N2) R226.2(N2) R230.1 S7.3(NO) U26.7
A5N_FB: C148.2(N2) R228.2(N2) R232.1 S8.3(NO) U27.7
A6N_FB: C160.2(N2) R254.2(N2) R258.1 S9.3(NO) U28.7
A7N_FB: C162.2(N2) R256.2(N2) R260.1 S10.3(NO) U29.7
ADAU1966A_RESET_SOM_A*: U8.6 U39.10
ADAU1966A_RESET_SOM_B*: U39.11 U51.6
ADAU1979_A_RESET_SOM_A*: U8.5 U35.10
ADAU1979_A_RESET_SOM_B*: U35.11 U51.5
ADAU1979_B_RESET_SOM_A*: U8.4 U37.10
ADAU1979_B_RESET_SOM_B*: U37.11 U51.4
ADAU_CLK: R123.1 U35.12
ADAU_CLK2: R582.1 U37.12
ADC1_BCLK: U20.5 U34.4
ADC1_LRCLK: U20.4 U34.7
ADC1_RESET*: R124.1 U16.3 U35.9
ADC1_ROUTE: R504.1 R509.1 U8.9 U34.1 U35.1
ADC1_SDATAOUT1: U20.2 U34.12
ADC1_SDATAOUT2: U20.3 U34.9
ADC1_TWI_SCL: U16.4 U35.4
ADC1_TWI_SDA: U16.5 U35.7
ADC2_BCLK: U21.5 U36.4
ADC2_LRCLK: U21.4 U36.7
ADC2_RESET*: R125.1 U17.3 U37.9
ADC2_ROUTE: R505.1 R510.1 U8.10 U36.1 U37.1
ADC2_SDATAOUT1: U21.2 U36.12
ADC2_SDATAOUT2: U21.3 U36.9
ADC2_TWI_SCL: U17.4 U37.4
ADC2_TWI_SDA: U17.5 U37.7
ADC_CHANNEL_0: P15.34 P16.12
ADC_CHANNEL_1: P15.33 P16.23
ADC_CHANNEL_2: P15.24 P16.9(N9)
ADC_CHANNEL_3: P15.23 P16.20
ADC_CHANNEL_4: P15.4 P16.6
ADC_CHANNEL_5: P15.3 P16.17
ADC_CHANNEL_6: P13.4 P16.3
ADC_CHANNEL_7: P13.3 P16.14
AIN0N: C115.P P15.35 R155.1
AIN0N_BUFFERED: C122.N(N2) R178.1 U18.33
AIN0P: C113.P P16.24 R153.1
AIN0P_BUFFERED: C121.N(N2) R177.1 U18.32
AIN1N: C116.P P15.32 R156.1
AIN1N_BUFFERED: C124.N(N2) R180.1 U18.35
AIN1P: C114.P P16.10 R154.1
AIN1P_BUFFERED: C123.N(N2) R179.1 U18.34
AIN2N: C129.P P15.25(N9) R183.1
AIN2N_BUFFERED: C136.N(N2) R206.1 U18.37
AIN2P: C127.P P16.21 R181.1
AIN2P_BUFFERED: C135.N(N2) R205.1 U18.36
AIN3N: C130.P P15.22 R184.1
AIN3N_BUFFERED: C138.N(N2) R208.1 U18.39
AIN3P: C128.P P16.7 R182.1
AIN3P_BUFFERED: C137.N(N2) R207.1 U18.38
AIN4N: C143.P P15.5 R211.1
AIN4N_BUFFERED: C150.N(N2) R234.1 U19.33
AIN4P: C141.P P16.18 R209.1
AIN4P_BUFFERED: C149.N(N2) R233.1 U19.32
AIN5N: C144.P P15.2 R212.1
AIN5N_BUFFERED: C152.N(N2) R236.1 U19.35
AIN5P: C142.P P16.4 R210.1
AIN5P_BUFFERED: C151.N(N2) R235.1 U19.34
AIN6N: C157.P P13.5 R239.1
AIN6N_BUFFERED: C164.N(N2) R262.1 U19.37
AIN6P: C155.P P16.15 R237.1
AIN6P_BUFFERED: C163.N(N2) R261.1 U19.36
AIN7N: C158.P P13.2 R240.1
AIN7N_BUFFERED: C166.N(N2) R264.1 U19.39
AIN7P: C156.P P16.1 R238.1
AIN7P_BUFFERED: C165.N(N2) R263.1 U19.38
AUDIO_VREF_ADC_1: A1.1 A1.4 R159.1 R162.1 R165.1 R168.1 R187.1 R190.1 R193.1 R196.1
AUDIO_VREF_ADC_2: A2.1 A2.4 R215.1 R218.1 R221.1 R224.1 R243.1 R246.1 R249.1 R252.1
BRD_PWR_EN: P32.1 P33.1 R461.2(N2)
CAN0_RX_SOM_A: SOMA.178 U41.3
CAN0_RX_SOM_B: SOMB.178 U43.3
CAN0_SILENT_SOM_A: R536.2(N2) R537.1 U41.4
CAN0_SILENT_SOM_B: R544.2(N2) R545.1 U43.4
CAN0_STBY_SOM_A: R535.2(N2) R538.1 SOMA.113 U41.6
CAN0_STBY_SOM_B: R543.2(N2) R553.1 SOMB.113 U43.6
CAN0_TX_SOM_A: SOMA.176 U41.5
CAN0_TX_SOM_B: SOMB.176 U43.5
CAN1_RX_SOM_A: SOMA.184 U42.3
CAN1_RX_SOM_B: SOMB.184 U44.3
CAN1_SILENT_SOM_A: R540.2(N2) R541.1 U42.4
CAN1_SILENT_SOM_B: R555.2(N2) R556.1 U44.4
CAN1_STBY_SOM_A: R539.2(N2) R542.1 SOMA.115 U42.6
CAN1_STBY_SOM_B: R554.2(N2) R557.1 SOMB.115 U44.6
CAN1_TX_SOM_A: SOMA.182 U42.5
CAN1_TX_SOM_B: SOMB.182 U44.5
CHANNEL_1: P13.24 P14.24A
CHANNEL_2: P13.23 P14.10A
CHANNEL_3: P13.34 P14.21A
CHANNEL_4: P13.33 P14.7A
CHANNEL_5: P12.4 P14.18A
CHANNEL_6: P12.3 P14.4A
CHANNEL_7: P12.24 P14.15A
CHANNEL_8: P12.23 P14.1A
CHANNEL_9: P12.34 P14.24B
CHANNEL_10: P12.33 P14.10B
CHANNEL_11: P11.4 P14.21B
CHANNEL_12: P11.3 P14.7B
CHANNEL_13: P11.24 P14.18B
CHANNEL_14: P11.23 P14.4B
CHANNEL_15: P11.34 P14.15B
CHANNEL_16: P11.33 P14.1B
DAC1N: R290.1 U33.51
DAC1N_OUT: C212.N(N2) P14.12A R298.1
DAC1P: R289.1 U33.50
DAC1P_OUT: C211.N(N2) P13.25(N9) R297.1
DAC2N: R292.1 U33.53
DAC2N_OUT: C214.N(N2) P14.23A R300.1
DAC2P: R291.1 U33.52
DAC2P_OUT: C213.N(N2) P13.22 R299.1
DAC3N: R286.1 U33.55
DAC3N_OUT: C208.N(N2) P14.9A R294.1
DAC3P: R285.1 U33.54
DAC3P_OUT: C207.N(N2) P13.35 R293.1
DAC4N: R288.1 U33.57
DAC4N_OUT: C210.N(N2) P14.20A R296.1
DAC4P: R287.1 U33.56
DAC4P_OUT: C209.N(N2) P13.32 R295.1
DAC5N: R306.1 U33.65
DAC5N_OUT: C228.N(N2) P14.6A R314.1
DAC5P: R305.1 U33.64
DAC5P_OUT: C227.N(N2) P12.5 R313.1
DAC6N: R308.1 U33.67
DAC6N_OUT: C230.N(N2) P14.17A R316.1
DAC6P: R307.1 U33.66
DAC6P_OUT: C229.N(N2) P12.2 R315.1
DAC7N: R302.1 U33.69
DAC7N_OUT: C224.N(N2) P14.3A R310.1
DAC7P: R301.1 U33.68
DAC7P_OUT: C223.N(N2) P12.25(N9) R309.1
DAC8N: R304.1 U33.71
DAC8N_OUT: C226.N(N2) P14.14A R312.1
DAC8P: R303.1 U33.70
DAC8P_OUT: C225.N(N2) P12.22 R311.1
DAC9N: R322.1 U33.73
DAC9N_OUT: C244.N(N2) P14.12B R330.1
DAC9P: R321.1 U33.72
DAC9P_OUT: C243.N(N2) P12.35 R329.1
DAC10N: R324.1 U33.75
DAC10N_OUT: C246.N(N2) P14.23B R332.1
DAC10P: R323.1 U33.74
DAC10P_OUT: C245.N(N2) P12.32 R331.1
DAC11N: R318.1 U33.77
DAC11N_OUT: C240.N(N2) P14.9B(N9) R326.1
DAC11P: R317.1 U33.76
DAC11P_OUT: C239.N(N2) P11.5 R325.1
DAC12N: R320.1 U33.79
DAC12N_OUT: C242.N(N2) P14.20B R328.1
DAC12P: R319.1 U33.78
DAC12P_OUT: C241.N(N2) P11.2 R327.1
DAC13N: R334.1 U33.5
DAC13N_OUT: C252.N(N2) P14.6B R338.1
DAC13P: R333.1 U33.4
DAC13P_OUT: C251.N(N2) P11.25(N9) R337.1
DAC14N: R336.1 U33.7
DAC14N_OUT: C254.N(N2) P14.17B R340.1
DAC14P: R335.1 U33.6
DAC14P_OUT: C253.N(N2) P11.22 R339.1
DAC15N: R342.1 U33.9
DAC15N_OUT: C260.N(N2) P14.3B R346.1
DAC15P: R341.1 U33.8
DAC15P_OUT: C259.N(N2) P11.35 R345.1
DAC16N: R344.1 U33.11
DAC16N_OUT: C262.N(N2) P14.14B R348.1
DAC16P: R343.1 U33.10
DAC16P_OUT: C261.N(N2) P11.32 R347.1
DAC_AUDIO_CLK: R281.1 U32.8
DAC_CLK: R265.1 U39.12
DAC_DBCLK: U30.2 U38.4
DAC_DLRCLK: U30.3 U38.7
DAC_DSDATA1: U30.4 U38.9
DAC_DSDATA2: U30.5 U38.12
DAC_DSDATA3: U31.2 U40.4
DAC_DSDATA4: U31.3 U40.7
DAC_DSDATA5: U31.4 U40.9
DAC_DSDATA6: U31.5 U40.12
DAC_MCLKO: R577.1 S16.5A S16.6A
DAC_RESET*: R266.1 U32.5 U39.9
DAC_ROUTE: R506.1 R511.1 U8.11 U38.1 U39.1 U40.1
DAC_TWI_SCL: U32.3 U39.4
DAC_TWI_SDA: U32.2 U39.7
DAI0_PIN01_SOM_A: SOMA.29 U34.3
DAI0_PIN01_SOM_B: SOMB.29 U34.2
DAI0_PIN02_SOM_A: SOMA.31 U34.6
DAI0_PIN02_SOM_B: SOMB.31 U34.5
DAI0_PIN03_SOM_A: SOMA.33 U35.13 U37.13
DAI0_PIN03_SOM_B: SOMB.33 U35.14 U37.14
DAI0_PIN04_SOM_A: SOMA.35 U34.10
DAI0_PIN04_SOM_B: SOMB.35 U34.11
DAI0_PIN05_SOM_A: SOMA.37 U34.13
DAI0_PIN05_SOM_B: SOMB.37 U34.14
DAI0_PIN06_SOM_A: SOMA.39 U36.3
DAI0_PIN06_SOM_B: SOMB.39 U36.2
DAI0_PIN07_SOM_A: SOMA.41 U36.6
DAI0_PIN07_SOM_B: SOMB.41 U36.5
DAI0_PIN08_SOM_A: SOMA.43 U36.10
DAI0_PIN08_SOM_B: SOMB.43 U36.11
DAI0_PIN09_SOM_A: SOMA.45 U36.13
DAI0_PIN09_SOM_B: SOMB.45 U36.14
DAI0_PIN10_SOM_A: R1.1 SOMA.47
DAI0_PIN10_SOM_B: R8.1 SOMB.47
DAI0_PIN11_SOM_A: J4.4 P20.1 SOMA.30
DAI0_PIN11_SOM_B: P3.4 P39.1 SOMB.30
DAI0_PIN12_SOM_A: J4.8 P20.3 SOMA.32
DAI0_PIN12_SOM_B: P3.8 P39.3 SOMB.32
DAI0_PIN13_SOM_A: J4.12 P20.5 SOMA.34
DAI0_PIN13_SOM_B: P3.12 P39.5 SOMB.34
DAI0_PIN14_SOM_A: J4.16 P20.7 SOMA.36
DAI0_PIN14_SOM_B: P3.16 P39.7 SOMB.36
DAI0_PIN15_SOM_A: J4.20 P20.9(N9) SOMA.38
DAI0_PIN15_SOM_B: P3.20 P39.9(N9) SOMB.38
DAI0_PIN16_SOM_A: J4.24 P20.11 SOMA.40
DAI0_PIN16_SOM_B: P3.24 P39.11 SOMB.40
DAI0_PIN17_SOM_A: J4.28 P20.13 SOMA.42
DAI0_PIN17_SOM_B: P3.28 P39.13 SOMB.42
DAI0_PIN18_SOM_A: J4.32 P20.15 SOMA.44
DAI0_PIN18_SOM_B: P3.32 P39.15 SOMB.44
DAI0_PIN19_SOM_A: P20.17 SOMA.46 U67.4
DAI0_PIN19_SOM_A_A2B: J4.36 U67.3
DAI0_PIN19_SOM_B: P39.17 SOMB.46 U69.4
DAI0_PIN19_SOM_B_A2B: P3.36 U69.3
DAI0_PIN20_SOM_A: P20.19 SOMA.48 U67.9
DAI0_PIN20_SOM_A_A2B: J4.40 U67.10
DAI0_PIN20_SOM_B: P39.19 SOMB.48 U69.9
DAI0_PIN20_SOM_B_A2B: P3.40 U69.10
DAI1_PIN01_SOM_A: SOMA.51 U38.3
DAI1_PIN01_SOM_B: SOMB.51 U38.2
DAI1_PIN02_SOM_A: SOMA.53 U38.6
DAI1_PIN02_SOM_B: SOMB.53 U38.5
DAI1_PIN03_SOM_A: SOMA.55 U39.13
DAI1_PIN03_SOM_B: SOMB.55 U39.14
DAI1_PIN04_SOM_A: SOMA.57 U38.10
DAI1_PIN04_SOM_B: SOMB.57 U38.11
DAI1_PIN05_SOM_A: SOMA.59 U38.13
DAI1_PIN05_SOM_B: SOMB.59 U38.14
DAI1_PIN06_SOM_A: SOMA.61 U40.3
DAI1_PIN06_SOM_B: SOMB.61 U40.2
DAI1_PIN07_SOM_A: SOMA.63 U40.6
DAI1_PIN07_SOM_B: SOMB.63 U40.5
DAI1_PIN08_SOM_A: SOMA.65 U40.10
DAI1_PIN08_SOM_B: SOMB.65 U40.11
DAI1_PIN09_SOM_A: SOMA.67 U40.13
DAI1_PIN09_SOM_B: SOMB.67 U40.14
DAI1_PIN10_SOM_A: SOMA.69 U81.10
DAI1_PIN10_SOM_B: SOMB.69 U81.9
DAI1_PIN11_SOM_A: J5.4 P21.1 SOMA.52
DAI1_PIN11_SOM_B: P4.4 P40.1 SOMB.52
DAI1_PIN12_SOM_A: J5.8 P21.3 SOMA.54
DAI1_PIN12_SOM_B: P4.8 P40.3 SOMB.54
DAI1_PIN13_SOM_A: J5.12 P21.5 SOMA.56
DAI1_PIN13_SOM_B: P4.12 P40.5 SOMB.56
DAI1_PIN14_SOM_A: J5.16 P21.7 SOMA.58
DAI1_PIN14_SOM_B: P4.16 P40.7 SOMB.58
DAI1_PIN15_SOM_A: J5.20 P21.9(N9) SOMA.60
DAI1_PIN15_SOM_B: P4.20 P40.9(N9) SOMB.60
DAI1_PIN16_SOM_A: J5.24 P21.11 SOMA.62
DAI1_PIN16_SOM_B: P4.24 P40.11 SOMB.62
DAI1_PIN17_SOM_A: R400.1 SOMA.64
DAI1_PIN17_SOM_A_A2B: J5.28 P21.13 U45.3
DAI1_PIN17_SOM_B: R412.2(N2) SOMB.64
DAI1_PIN17_SOM_B_A2B: P4.28 P40.13 U47.3
DAI1_PIN18_SOM_A: R401.1 SOMA.66
DAI1_PIN18_SOM_A_A2B: J5.32 P21.15 U45.6
DAI1_PIN18_SOM_B: R413.2(N2) SOMB.66
DAI1_PIN18_SOM_B_A2B: P4.32 P40.15 U47.6
DAI1_PIN19_SOM_A: R402.1 SOMA.68
DAI1_PIN19_SOM_A_A2B: J5.36 P21.17 U45.10
DAI1_PIN19_SOM_B: R414.2(N2) SOMB.68
DAI1_PIN19_SOM_B_A2B: P4.36 P40.17 U47.10
DAI1_PIN20_SOM_A: R403.1 SOMA.70
DAI1_PIN20_SOM_A_A2B: J5.40 P21.19 U45.13
DAI1_PIN20_SOM_B: R415.2(N2) SOMB.70
DAI1_PIN20_SOM_B_A2B: P4.40 P40.19 U47.13
DAI1_ROUTE: R507.1 R512.1 U8.12 U45.1 U47.1
E70_3V3: C321.1 C322.1 C324.1 C325.1 C326.1 C346.1 C348.1 C349.1 C350.1 C352.1 C353.1 C354.1 C355.1 C356.1 C357.1 C358.1 C359.1 C363.1 C364.1 C367.1 D12.4 DS20.A(P) E3.1 L8.2(N2) P10.1 P28.2(N2) P29.1 P34.1 R464.1 R466.1 R467.1 R468.1 R469.1 R470.1 R471.1 R475.1 R484.1 R485.1 R486.1 R497.2(N2) TP24.1(N1) U53.8 U54.B4 U54.C1 U54.D4 U54.D6 U54.F10 U54.K6 U55.3 U55.6 U56.4(VCC) U57.A1 U57.B1 U58.1 U58.2 U58.3 U59.1 U59.7 U59.10 U60.1
E70_FLASH_CS_N: R464.2(N2) U53.1 U54.N10
E70_FLASH_D2: R467.2(N2) U53.3(WP#(IO2)) U54.J4
E70_FLASH_D3: R469.2(N2) U53.7 U54.C3
E70_FLASH_MISO: U53.5 U54.N11
E70_FLASH_MOSI: R466.2(N2) U53.2 U54.M4
E70_FLASH_SCK: R465.1 U53.6 U54.M6
E70_RESET_N: P34.10(N5) R470.2(N2) R485.2(N2) R487.2(N2) U54.K12 U56.2
E70_SWCLK/TCK: P34.4 U54.H13
E70_SWDIO/TMS: P34.2 U54.K11
E70_TARGET_RESET_N: R484.2(N2) U56.3
E70_TDI: P34.8 U54.C13
E70_TRACESW0/TDO: P34.6 U54.C12
E70_USBDM: D13.1 P9.A7 P9.B7 U54.A5
E70_USBDP: D13.3 P9.A6 P9.B6 U54.A4
E70_VBG: C323.1 R463.1 U54.A3
E70_VDDCORE: C328.1 C330.1 C331.1 C332.1 C334.1 C337.1 C340.1 E4.2(N2) E5.2(N2) U54.D5 U54.E4 U54.G10 U54.K5
EEPROM_WP: R590.1 S15.1 U10.5(WP) U76.5(WP)
ETH0_LINK_LED: R79.1 R80.2(N2) R82.2(N2) U1.21
ETH0_MD_INT_SOM_A: SOMA.75 U11.4
ETH0_MD_INT_Z: R78.2(N2) U1.22 U11.2
ETH0_MDC_SOM_A: R62.1 SOMA.125 U1.23
ETH0_MDIO_SOM_A: R81.2(N2) SOMA.123 U1.24
ETH0_MDIX_MODE: R74.1 R75.2(N2) U1.27
ETH0_PHY_CFG1: R76.1 R77.2(N2) R83.2(N2) U1.26
ETH0_RESET*: U8.8 U80.2
ETH0_RESET_Z*: R68.2(N2) U1.7 U80.10
ETH0_RXCLK_REFCLK_SOM_A: R52.1 R53.2(N2) R65.1 SOMA.87
ETH0_RXCTL_CRS_SOM_A: R54.1 R55.2(N2) R70.1 SOMA.99
ETH0_RXD0_SOM_A: R63.1 R71.1 R72.2(N2) SOMA.77
ETH0_RXD1_SOM_A: R64.1 R66.1 R67.2(N2) SOMA.79
ETH0_RXD2_SOM_A: R60.1 R61.2(N2) R69.1 SOMA.81
ETH0_RXD3_SOM_A: R58.1 R59.2(N2) R73.1 SOMA.83
ETH0_TXCLK_SOM_A: SOMA.101 U1.38
ETH0_TXD0_SOM_A: SOMA.89 U1.39
ETH0_TXD1_SOM_A: SOMA.91 U1.1
ETH0_TXD2_SOM_A: SOMA.93 U1.2
ETH0_TXD3_SOM_A: SOMA.95 U1.3
ETH0_TXEN_SOM_A: SOMA.103 U1.37
ETH1_LINK_LED: R111.1 R112.2(N2) R114.2(N2) U2.21
ETH1_MD_INT_SOM_B: SOMB.75 U12.4
ETH1_MD_INT_Z: R110.2(N2) U2.22 U12.2
ETH1_MDC_SOM_B: R94.1 SOMB.125 U2.23
ETH1_MDIO_SOM_B: R113.2(N2) SOMB.123 U2.24
ETH1_MDIX_MODE: R106.1 R107.2(N2) U2.27
ETH1_PHY_CFG1: R108.1 R109.2(N2) R115.2(N2) U2.26
ETH1_RESET*: U51.8 U80.3
ETH1_RESET_Z*: R100.2(N2) U2.7 U80.9
ETH1_RXCLK_REFCLK_SOM_B: R84.1 R85.2(N2) R97.1 SOMB.87
ETH1_RXCTL_CRS_SOM_B: R86.1 R87.2(N2) R102.1 SOMB.99
ETH1_RXD0_SOM_B: R95.1 R103.1 R104.2(N2) SOMB.77
ETH1_RXD1_SOM_B: R96.1 R98.1 R99.2(N2) SOMB.79
ETH1_RXD2_SOM_B: R92.1 R93.2(N2) R101.1 SOMB.81
ETH1_RXD3_SOM_B: R90.1 R91.2(N2) R105.1 SOMB.83
ETH1_TXCLK_SOM_B: SOMB.101 U2.38
ETH1_TXD0_SOM_B: SOMB.89 U2.39
ETH1_TXD1_SOM_B: SOMB.91 U2.1
ETH1_TXD2_SOM_B: SOMB.93 U2.2
ETH1_TXD3_SOM_B: SOMB.95 U2.3
ETH1_TXEN_SOM_B: SOMB.103 U2.37
GPIO_00: P37.4 SOMA.19
GPIO_01: P37.6 SOMA.21
GPIO_02: P37.8 SOMA.23
GPIO_03: P37.10 SOMA.25
HADC_VIN0_SOM_A: P5.1 SOMA.74
HADC_VIN0_SOM_B: P6.1 SOMB.74
HADC_VIN1_SOM_A: P5.3 SOMA.76
HADC_VIN1_SOM_B: P6.3 SOMB.76
HADC_VIN2_SOM_A: P5.5 SOMA.78
HADC_VIN2_SOM_B: P6.5 SOMB.78
HADC_VIN3_SOM_A: P5.7 SOMA.80
HADC_VIN3_SOM_B: P6.7 SOMB.80
HADC_VIN4_SOM_A: P5.9(N9) SOMA.82
HADC_VIN4_SOM_B: P6.9(N9) SOMB.82
HADC_VIN5_SOM_A: P5.11 SOMA.84
HADC_VIN5_SOM_B: P6.11 SOMB.84
HADC_VIN6_SOM_A: P5.13 SOMA.86
HADC_VIN6_SOM_B: P6.13 SOMB.86
HADC_VIN7_SOM_A: P5.15 SOMA.88
HADC_VIN7_SOM_B: P6.15 SOMB.88
ID0: R471.2(N2) R472.1 U15.9
ID0_SOMA: SOMA.264 U15.10
ID0_SOMB: SOMB.264 U15.11
ID1: R468.2(N2) U15.12 U54.G11
ID1_SOMA: SOMA.266 U15.13
ID1_SOMB: SOMB.266 U15.14
JTAG_1V8: C360.1 C361.1 C362.1 P10.3(N3) R498.2(N2) U57.A2(VOUT)
JTAG_DAISY_CHAIN*: S1.2 U9.1 U9.4 U9.10 U9.13 U52.1 U60.10
JTAG_DAISY_CHAIN_DETECT: R599.2(N2) U60.7
JTAG_EMU*: R475.2(N2) R500.1 U54.C7
JTAG_EMU_CONN*: R488.2(N2) S11.8 U60.11
JTAG_EN: R496.1 U54.F2 U58.14 U58.15 U59.2 U60.14 U60.15
JTAG_IO: C365.1 C366.1 C368.1 P10.2 R488.1 R490.1 R497.1 R498.1 U58.16(VCCB) U59.6(VCCB) U60.16(VCCB)
JTAG_PD: R501.1 U54.G1
JTAG_PD_CONN: R489.2(N2) U60.13
JTAG_SOM_ROUTE: S2.2 U14.1 U15.1
JTAG_SPI_CS_N: U54.C6 U54.L6
JTAG_TARGET_RESET_N: U54.G3 U59.8 U59.9
JTAG_TARGET_RESET_N_CONN: R490.2(N2) R491.1 S11.10 U59.4 U59.5
JTAG_TARGET_RESET_SOM_A*: SOMA.146 U15.6
JTAG_TARGET_RESET_SOM_B*: SOMB.146 U15.5
JTAG_TCK: R474.2(N2) U54.D7 U58.5
JTAG_TCK_CONN: R494.2(N2) S11.13
JTAG_TCK_SOM_A: SOMA.138 U9.5 U14.13
JTAG_TCK_SOM_B: SOMB.138 U9.6 U14.14
JTAG_TDI: U54.F4 U58.6
JTAG_TDI_CONN: R493.2(N2) S11.11
JTAG_TDI_SOM_A: SOMA.142 U14.10
JTAG_TDI_SOM_B: SOMB.142 U52.7
JTAG_TDI_SOM_B_Z: U14.11 U52.6
JTAG_TDI_TDO_SOM_B: U52.2 U52.5
JTAG_TDO: R499.1 U54.K9
JTAG_TDO_CONN: S11.12 U60.12
JTAG_TDO_SOM_A: SOMA.140 U52.4
JTAG_TDO_SOM_A_Z: U14.6 U52.3 U52.11
JTAG_TDO_SOM_B: SOMB.140 U52.9
JTAG_TDO_SOM_B_Z: U14.5 U52.10
JTAG_TMS: U54.L9 U58.4
JTAG_TMS_CONN: R492.2(N2) S11.14
JTAG_TMS_SOM_A: SOMA.136 U9.2 U14.3
JTAG_TMS_SOM_B: SOMB.136 U9.3 U14.2
JTAG_TRST_N: U54.H1 U58.7
JTAG_TRST_N_CONN: R495.2(N2) S11.15
JTAG_TRST_SOM_A*: SOMA.144 U9.9 U15.3
JTAG_TRST_SOM_B*: SOMB.144 U9.8 U15.2
JTG0_TARGET_RESET*: R532.1 R583.2(N2) S11.7 U15.7
JTG0_TCK/SWCLK_LOCAL: P8.4 P35.4 S11.4 U14.12
JTG0_TDI_LOCAL: P8.8 P35.8 S11.6 U14.9
JTG0_TDO_LOCAL: P8.6 P35.6 S11.5 U14.7
JTG0_TMS/SWDIO_LOCAL: P8.2 P35.2 S11.3 U14.4
JTG0_TRST_LOCAL*: P8.9(N9) R523.1 R528.2(N2) R584.2(N2) S11.2 U15.4
LED_BLUE: R478.1 U54.G13
LED_GREEN: R476.1 U54.D13
LED_RED: R477.1 U54.E13
LINKPORT0_ACK_SOM_A: R377.1 SOMA.255
LINKPORT0_ACK_SOM_B: R393.2(N2) SOMB.255
LINKPORT0_CLK_SOM_A: R376.1 SOMA.253
LINKPORT0_CLK_SOM_B: R392.2(N2) SOMB.253
LINKPORT0_D0_SOM_A: R372.1 SOMA.257
LINKPORT0_D0_SOM_B: R388.2(N2) SOMB.257
LINKPORT0_D1_SOM_A: R373.1 SOMA.259
LINKPORT0_D1_SOM_B: R389.2(N2) SOMB.259
LINKPORT0_D2_SOM_A: R374.1 SOMA.261
LINKPORT0_D2_SOM_B: R390.2(N2) SOMB.261
LINKPORT0_D3_SOM_A: R375.1 SOMA.263
LINKPORT0_D3_SOM_B: R391.2(N2) SOMB.263
LINKPORT1_ACK_SOM_A: R383.1 SOMA.269
LINKPORT1_ACK_SOM_B: R399.2(N2) SOMB.269
LINKPORT1_CLK_SOM_A: R382.1 SOMA.267
LINKPORT1_CLK_SOM_B: R398.2(N2) SOMB.267
LINKPORT1_D0_SOM_A: R378.1 SOMA.271
LINKPORT1_D0_SOM_B: R394.2(N2) SOMB.271
LINKPORT1_D1_SOM_A: R379.1 SOMA.273
LINKPORT1_D1_SOM_B: R395.2(N2) SOMB.273
LINKPORT1_D2_SOM_A: R380.1 SOMA.275
LINKPORT1_D2_SOM_B: R396.2(N2) SOMB.275
LINKPORT1_D3_SOM_A: R381.1 SOMA.277
LINKPORT1_D3_SOM_B: R397.2(N2) SOMB.277
MDI_0_N: D1.3 P1.10 U1.13
MDI_0_N_A: D3.3 P2.10 U2.13
MDI_0_P: D1.1 P1.11 U1.12
MDI_0_P_A: D3.1 P2.11 U2.12
MDI_1_N: D1.6 P1.5 U1.15
MDI_1_N_A: D3.6 P2.5 U2.15
MDI_1_P: D1.4 P1.4 U1.14
MDI_1_P_A: D3.4 P2.4 U2.14
MDI_2_N: D2.3 P1.2 U1.17
MDI_2_N_A: D4.3 P2.2 U2.17
MDI_2_P: D2.1 P1.3 U1.16
MDI_2_P_A: D4.1 P2.3 U2.16
MDI_3_N: D2.6 P1.9(N9) U1.19
MDI_3_N_A: D4.6 P2.9(N9) U2.19
MDI_3_P: D2.4 P1.8 U1.18
MDI_3_P_A: D4.4 P2.8 U2.18
MLB_CLK_SOM_A: DS1.A(P) P38.1 SOMA.168
MLB_CLK_SOM_B: DS4.A(P) P42.1 SOMB.168
MLB_DAT_SOM_A: DS3.A(P) P38.3 SOMA.172
MLB_DAT_SOM_B: DS6.A(P) P42.3 SOMB.172
MLB_SIG_SOM_A: DS2.A(P) P38.2 SOMA.170
MLB_SIG_SOM_B: DS5.A(P) P42.2 SOMB.170
PB1_LED: SOMA.105 U79.2
PB1_LED_X: R600.2(N2) U79.10
PB2_LED: SOMA.107 U79.3
PB2_LED_X: R601.2(N2) U79.9
PB3_LED: SOMB.105 U79.4
PB3_LED_X: R602.2(N2) U79.8
PB4_LED: SOMB.107 U79.5
PB4_LED_X: R603.2(N2) U79.7
PUSHBUTTON_A_1: SOMA.106 U7.3
PUSHBUTTON_A_2: SOMA.108 U7.6
PUSHBUTTON_A_EN*: R24.2(N2) R25.1 U7.1 U7.4 U8.3
PUSHBUTTON_B_1: SOMB.106 U7.8
PUSHBUTTON_B_2: SOMB.108 U7.11
PUSHBUTTON_B_EN*: R21.2(N2) R22.1 U7.10 U7.13 U51.3
QSPI_CITO_SOM_A: R405.1 SOMA.94
QSPI_CITO_SOM_A_A2B: J4.63 J5.64 U46.6
QSPI_CITO_SOM_B: P4.64 R417.2(N2) SOMB.94
QSPI_CITO_SOM_B_A2B: P3.63 U48.6
QSPI_CLK_SOM_A: R404.1 SOMA.92
QSPI_CLK_SOM_A_A2B: J4.71 J5.72 U46.3
QSPI_CLK_SOM_B: P4.72 R416.2(N2) SOMB.92
QSPI_CLK_SOM_B_A2B: P3.71 U48.3
QSPI_COTI_SOM_A: R406.1 SOMA.96
QSPI_COTI_SOM_A_A2B: J4.67 J5.68 U46.10
QSPI_COTI_SOM_B: P4.68 R418.2(N2) SOMB.96
QSPI_COTI_SOM_B_A2B: P3.67 U48.10
QSPI_D2_SOM_A: R520.1 SOMA.98
QSPI_D2_SOM_B: R526.2(N2) SOMB.98
QSPI_D3_SOM_A: R521.1 SOMA.100
QSPI_D3_SOM_B: R527.2(N2) SOMB.100
QSPI_ROUTE: R508.1 R513.1 U8.13 U46.1 U48.1 U61.1 U62.1
QSPI_SEL1_SOM_A: R407.1 SOMA.102
QSPI_SEL1_SOM_A_A2B: J4.75 J5.80 U46.13
QSPI_SEL1_SOM_B: P4.80 R419.2(N2) SOMB.102
QSPI_SEL1_SOM_B_A2B: P3.75 U48.13
QSPI_SEL2_SOM_A: J4.79 J5.76 SOMA.104
QSPI_SEL2_SOM_B: P3.79 P4.76 SOMB.104
REG_EN: P17.2 R440.1 R459.2(N2) U3.10 U4.10 U49.10 U50.10 U77.10 U78.10
SPDIF1_COAX_EN*: U8.1 U74.4 U74.13
SPDIF1_EN*: U8.7 U67.1
SPDIF1_IN_COAX: U63.9 U70.7
SPDIF1_IN_OPT: M1.3(VOUT) U63.10
SPDIF1_OPT_EN*: U8.2 U74.1 U74.10
SPDIF1_OUT_COAX: U63.7 U71.1 U71.2
SPDIF1_OUT_OPT: M1.4 U63.8
SPDIF2_COAX_EN*: U51.1 U75.4 U75.13
SPDIF2_EN*: U51.7 U69.1
SPDIF2_IN_COAX: U68.9 U72.7
SPDIF2_IN_OPT: M2.3(VOUT) U68.10
SPDIF2_OPT_EN*: U51.2 U75.1 U75.10
SPDIF2_OUT_COAX: U68.7 U73.1 U73.2
SPDIF2_OUT_OPT: M2.4 U68.8
SPI_CITO_SOM_A: J4.64 J5.63 P30.7 P32.4 SOMA.114
SPI_CITO_SOM_B: P3.64 P4.63 P31.7 P33.4 SOMB.114
SPI_CLK_SOM_A: J4.72 J5.71 P30.9 P32.2 SOMA.112
SPI_CLK_SOM_B: P3.72 P4.71 P31.9 P33.2 SOMB.112
SPI_COTI_SOM_A: J4.68 J5.67 P30.10 P32.6 SOMA.116
SPI_COTI_SOM_B: P3.68 P4.67 P31.10 P33.6 SOMB.116
SPI_RDY_SOM_A: P32.12 SOMA.122
SPI_RDY_SOM_B: P33.12 SOMB.122
SPI_SEL1_SOM_A: J4.76 J5.79 P32.8 SOMA.118
SPI_SEL1_SOM_B: P3.76 P4.79 P33.8 SOMB.118
SPI_SEL2_SOM_A: J4.80 J5.75 P30.11 P32.10 SOMA.120
SPI_SEL2_SOM_B: P3.80 P4.75 P31.11 P33.10 SOMB.120
SYS_HWRST*: R31.2(N2) R32.2(N2) R515.2(N2) R518.2(N2) R551.2(N2) R552.2(N2) R586.2(N2) R587.2(N2) U8.20 U51.20 U65.A2 U65.A4 U66.8
TARGET_RESET*: P32.3 P33.3 R547.2(N2) U64.2
TRACE_CLK: P35.12 SOMA.1
TRACE_D00: P35.14 SOMA.3
TRACE_D01: P35.16 SOMA.5
TRACE_D02: P35.18(N9) SOMA.7
TRACE_D03: P35.20 SOMA.9
TRACE_D04: P37.3 SOMA.11
TRACE_D05: P37.5 SOMA.13
TRACE_D06: P37.7 SOMA.15
TRACE_D07: P37.9(N9) SOMA.17
TWI0_SCL_SOM_A: J4.88 R3.2(N2) R588.2(N2) S12.1A SOMA.152 U76.1
TWI0_SCL_SOM_B: P3.88 R529.2(N2) R559.2(N2) S13.1A SOMB.152 U10.1
TWI0_SDA_SOM_A: J4.84 R2.2(N2) R589.2(N2) S12.2A SOMA.150 U76.3
TWI0_SDA_SOM_B: P3.84 R530.2(N2) R558.2(N2) S13.2A SOMB.150 U10.3
TWI1_SCL_SOM_A: J5.88 R5.2(N2) S12.4A SOMA.158
TWI1_SCL_SOM_B: P4.88 R561.2(N2) S13.4A SOMB.158
TWI1_SDA_SOM_A: J5.84 R4.2(N2) S12.5A SOMA.156
TWI1_SDA_SOM_B: P4.84 R560.2(N2) S13.5A SOMB.156
TWI2_SCL_SOM_A: R7.2(N2) S12.7A SOMA.164 U8.23 U35.3 U37.3 U39.3
TWI2_SCL_SOM_B: R563.2(N2) S13.7A SOMB.164 U35.2 U37.2 U39.2 U51.23
TWI2_SDA_SOM_A: R6.2(N2) S12.8A SOMA.162 U8.22 U35.6 U37.6 U39.6
TWI2_SDA_SOM_B: R562.2(N2) S13.8A SOMB.162 U35.5 U37.5 U39.5 U51.22
UART0_CTS_SOM_A*: P26.6(N6) R436.1 SOMA.194
UART0_CTS_SOM_B*: P27.6(N6) R437.1 SOMB.194
UART0_RTS_SOM_A*: P26.2 SOMA.192
UART0_RTS_SOM_B*: P27.2 SOMB.192
UART0_RX_SOM_A*: P26.4 SOMA.190
UART0_RX_SOM_B*: P27.4 SOMB.190
UART0_TX_SOM_A*: P26.5 SOMA.188
UART0_TX_SOM_B*: P27.5 SOMB.188
UART1_CTS_SOM_A*: P22.6(N6) R432.1 SOMA.204
UART1_CTS_SOM_B*: P23.6(N6) R433.1 SOMB.204
UART1_RTS_SOM_A*: P22.2 SOMA.202
UART1_RTS_SOM_B*: P23.2 SOMB.202
UART1_RX_SOM_A*: P22.4 SOMA.200
UART1_RX_SOM_B*: P23.4 SOMB.200
UART1_TX_SOM_A*: P22.5 SOMA.198
UART1_TX_SOM_B*: P23.5 SOMB.198
UART2_CTS_SOM_A*: P24.6(N6) R434.1 SOMA.214
UART2_CTS_SOM_B*: P25.6(N6) R435.1 SOMB.214
UART2_RTS_SOM_A*: P24.2 SOMA.212
UART2_RTS_SOM_B*: P25.2 SOMB.212
UART2_RX_SOM_A*: P24.4 SOMA.210
UART2_RX_SOM_B*: P25.4 SOMB.210
UART2_TX_SOM_A*: P24.5 SOMA.208
UART2_TX_SOM_B*: P25.5 SOMB.208
UNNAMED_4_ADLT8609_I14_BST: C312.2(N2) U4.1
UNNAMED_4_ADLT8609_I14_FB: C316.1 R454.1 R456.1 U4.6
UNNAMED_4_ADLT8609_I14_INTVCC: C310.1 U4.3
